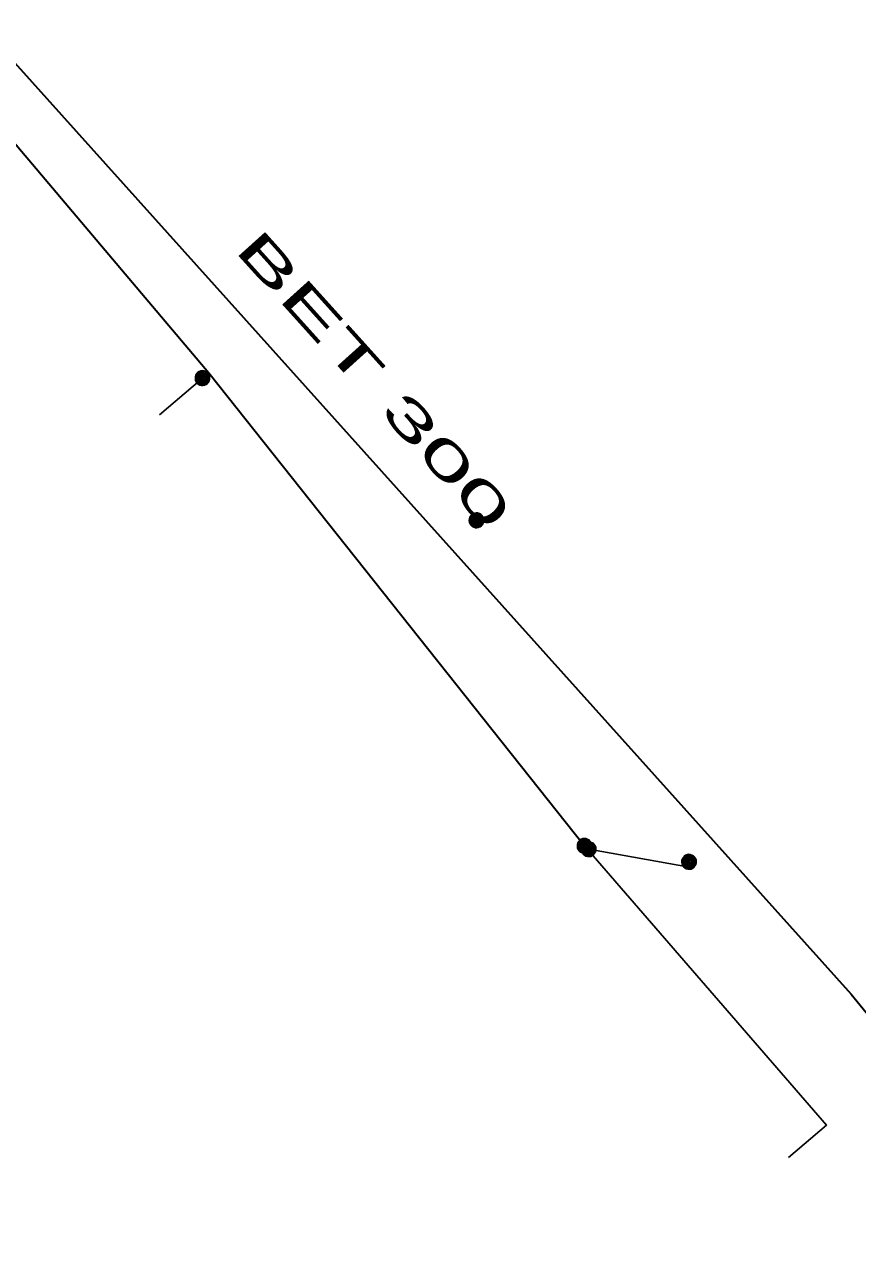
# Model space of a CAD drawing. Extents: x -873619 to -867639, y -1015082 to -1012326.
# Drawn here: x -867922.2 to -867896.54, y -1012817 to -1012778.98 of the extents above; entities that cross this region are included whole.
import ezdxf

# ---------------------------------------------------------------- set-up
doc = ezdxf.new("R2010")
doc.units = 0
doc.header["$LTSCALE"] = 0.44
for name, color, linetype, lineweight in [('1', 7, 'Continuous', 13), ('12', 7, 'Continuous', 13), ('21', 7, 'Continuous', 35), ('25', 7, 'Continuous', 13), ('3', 7, 'Continuous', 25)]:
    doc.layers.add(name, color=color, linetype=linetype, lineweight=lineweight)

msp = doc.modelspace()

# ---------------------------------------------------------------- linework, layer by layer
at = {"layer": '1', "lineweight": 35}
msp.add_lwpolyline([(-867974.611, -1012725.697), (-867974.301, -1012725.775), (-867973.868, -1012725.89), (-867972.988, -1012726.12), (-867972.44, -1012726.34), (-867942.73, -1012759.87), (-867932.66, -1012771.332), (-867928.969, -1012774.977), (-867916.529, -1012789.697), (-867904.95, -1012804.27)], dxfattribs=at)
at = {"layer": '12'}
for points in [[(-867916.489, -1012789.86), (-867916.495, -1012789.808), (-867916.512, -1012789.758), (-867916.541, -1012789.714), (-867916.578, -1012789.677), (-867916.623, -1012789.65), (-867916.673, -1012789.633), (-867916.726, -1012789.629), (-867916.777, -1012789.636), (-867916.826, -1012789.655), (-867916.87, -1012789.684), (-867916.906, -1012789.723), (-867916.932, -1012789.768), (-867916.948, -1012789.819), (-867916.951, -1012789.871), (-867916.943, -1012789.923), (-867916.923, -1012789.972), (-867916.892, -1012790.015), (-867916.853, -1012790.049), (-867916.807, -1012790.075), (-867916.755, -1012790.089), (-867916.703, -1012790.091), (-867916.652, -1012790.081), (-867916.603, -1012790.06), (-867916.561, -1012790.029), (-867916.527, -1012789.988), (-867916.503, -1012789.942), (-867916.49, -1012789.891)], [(-867916.519, -1012789.86), (-867916.525, -1012789.811), (-867916.542, -1012789.765), (-867916.57, -1012789.725), (-867916.607, -1012789.693), (-867916.651, -1012789.671), (-867916.699, -1012789.66), (-867916.748, -1012789.66), (-867916.794, -1012789.673), (-867916.838, -1012789.697), (-867916.874, -1012789.73), (-867916.901, -1012789.771), (-867916.917, -1012789.818), (-867916.921, -1012789.867), (-867916.914, -1012789.915), (-867916.895, -1012789.96), (-867916.865, -1012790), (-867916.826, -1012790.031), (-867916.782, -1012790.051), (-867916.735, -1012790.061), (-867916.686, -1012790.059), (-867916.639, -1012790.044), (-867916.596, -1012790.019), (-867916.561, -1012789.985), (-867916.536, -1012789.943), (-867916.522, -1012789.896)], [(-867916.549, -1012789.86), (-867916.554, -1012789.815), (-867916.571, -1012789.773), (-867916.6, -1012789.738), (-867916.636, -1012789.711), (-867916.678, -1012789.694), (-867916.723, -1012789.689), (-867916.767, -1012789.695), (-867916.809, -1012789.714), (-867916.843, -1012789.742), (-867916.87, -1012789.779), (-867916.887, -1012789.821), (-867916.891, -1012789.866), (-867916.884, -1012789.911), (-867916.865, -1012789.952), (-867916.836, -1012789.986), (-867916.799, -1012790.012), (-867916.755, -1012790.028), (-867916.711, -1012790.031), (-867916.666, -1012790.023), (-867916.625, -1012790.003), (-867916.592, -1012789.974), (-867916.566, -1012789.936), (-867916.552, -1012789.893)], [(-867916.579, -1012789.86), (-867916.583, -1012789.819), (-867916.602, -1012789.782), (-867916.629, -1012789.751), (-867916.664, -1012789.73), (-867916.704, -1012789.719), (-867916.745, -1012789.721), (-867916.784, -1012789.734), (-867916.818, -1012789.758), (-867916.843, -1012789.79), (-867916.858, -1012789.828), (-867916.86, -1012789.869), (-867916.853, -1012789.909), (-867916.833, -1012789.945), (-867916.804, -1012789.974), (-867916.767, -1012789.993), (-867916.727, -1012790.001), (-867916.686, -1012789.997), (-867916.647, -1012789.982), (-867916.615, -1012789.956), (-867916.593, -1012789.922), (-867916.58, -1012789.883)], [(-867916.608, -1012789.86), (-867916.614, -1012789.824), (-867916.632, -1012789.792), (-867916.657, -1012789.767), (-867916.691, -1012789.752), (-867916.728, -1012789.749), (-867916.762, -1012789.757), (-867916.794, -1012789.777), (-867916.816, -1012789.805), (-867916.83, -1012789.839), (-867916.83, -1012789.876), (-867916.819, -1012789.911), (-867916.798, -1012789.94), (-867916.767, -1012789.961), (-867916.733, -1012789.971), (-867916.696, -1012789.969), (-867916.662, -1012789.955), (-867916.635, -1012789.932), (-867916.615, -1012789.9), (-867916.608, -1012789.865)], [(-867916.639, -1012789.86), (-867916.644, -1012789.829), (-867916.661, -1012789.803), (-867916.686, -1012789.786), (-867916.717, -1012789.779), (-867916.748, -1012789.783), (-867916.775, -1012789.8), (-867916.793, -1012789.824), (-867916.801, -1012789.855), (-867916.797, -1012789.885), (-867916.782, -1012789.913), (-867916.757, -1012789.932), (-867916.728, -1012789.941), (-867916.696, -1012789.938), (-867916.669, -1012789.924), (-867916.649, -1012789.9), (-867916.639, -1012789.871)], [(-867916.669, -1012789.86), (-867916.674, -1012789.836), (-867916.691, -1012789.818), (-867916.713, -1012789.809), (-867916.738, -1012789.812), (-867916.759, -1012789.826), (-867916.77, -1012789.848), (-867916.77, -1012789.873), (-867916.757, -1012789.894), (-867916.738, -1012789.908), (-867916.713, -1012789.911), (-867916.69, -1012789.902), (-867916.674, -1012789.884)], [(-867916.699, -1012789.86), (-867916.704, -1012789.845), (-867916.718, -1012789.839), (-867916.733, -1012789.843), (-867916.74, -1012789.857), (-867916.737, -1012789.872), (-867916.723, -1012789.881), (-867916.708, -1012789.878), (-867916.699, -1012789.866)], [(-867904.718, -1012804.27), (-867904.725, -1012804.218), (-867904.742, -1012804.168), (-867904.771, -1012804.124), (-867904.808, -1012804.087), (-867904.853, -1012804.06), (-867904.902, -1012804.043), (-867904.956, -1012804.039), (-867905.007, -1012804.046), (-867905.056, -1012804.065), (-867905.1, -1012804.094), (-867905.136, -1012804.133), (-867905.162, -1012804.178), (-867905.178, -1012804.229), (-867905.181, -1012804.281), (-867905.173, -1012804.333), (-867905.152, -1012804.382), (-867905.122, -1012804.425), (-867905.083, -1012804.459), (-867905.037, -1012804.485), (-867904.985, -1012804.499), (-867904.933, -1012804.501), (-867904.882, -1012804.491), (-867904.833, -1012804.47), (-867904.791, -1012804.439), (-867904.757, -1012804.398), (-867904.733, -1012804.352), (-867904.72, -1012804.301)], [(-867904.749, -1012804.27), (-867904.755, -1012804.221), (-867904.772, -1012804.175), (-867904.799, -1012804.135), (-867904.837, -1012804.103), (-867904.88, -1012804.081), (-867904.929, -1012804.07), (-867904.978, -1012804.07), (-867905.024, -1012804.083), (-867905.068, -1012804.107), (-867905.103, -1012804.14), (-867905.13, -1012804.181), (-867905.147, -1012804.228), (-867905.151, -1012804.277), (-867905.144, -1012804.325), (-867905.125, -1012804.37), (-867905.095, -1012804.41), (-867905.056, -1012804.441), (-867905.012, -1012804.461), (-867904.965, -1012804.471), (-867904.916, -1012804.469), (-867904.869, -1012804.454), (-867904.826, -1012804.429), (-867904.791, -1012804.395), (-867904.766, -1012804.353), (-867904.752, -1012804.306)], [(-867904.779, -1012804.27), (-867904.784, -1012804.225), (-867904.801, -1012804.183), (-867904.83, -1012804.148), (-867904.865, -1012804.121), (-867904.907, -1012804.104), (-867904.953, -1012804.099), (-867904.997, -1012804.105), (-867905.039, -1012804.124), (-867905.073, -1012804.152), (-867905.1, -1012804.189), (-867905.117, -1012804.231), (-867905.12, -1012804.276), (-867905.114, -1012804.321), (-867905.095, -1012804.362), (-867905.066, -1012804.396), (-867905.029, -1012804.422), (-867904.985, -1012804.438), (-867904.941, -1012804.441), (-867904.896, -1012804.433), (-867904.855, -1012804.413), (-867904.821, -1012804.384), (-867904.796, -1012804.346), (-867904.782, -1012804.303)], [(-867904.809, -1012804.27), (-867904.813, -1012804.229), (-867904.831, -1012804.192), (-867904.858, -1012804.161), (-867904.894, -1012804.14), (-867904.934, -1012804.129), (-867904.975, -1012804.131), (-867905.014, -1012804.144), (-867905.048, -1012804.168), (-867905.073, -1012804.2), (-867905.088, -1012804.238), (-867905.09, -1012804.279), (-867905.083, -1012804.319), (-867905.063, -1012804.355), (-867905.034, -1012804.384), (-867904.997, -1012804.403), (-867904.956, -1012804.411), (-867904.916, -1012804.407), (-867904.877, -1012804.392), (-867904.845, -1012804.366), (-867904.823, -1012804.332), (-867904.809, -1012804.293)], [(-867904.838, -1012804.27), (-867904.843, -1012804.234), (-867904.862, -1012804.202), (-867904.887, -1012804.177), (-867904.921, -1012804.162), (-867904.958, -1012804.159), (-867904.992, -1012804.167), (-867905.024, -1012804.187), (-867905.046, -1012804.215), (-867905.059, -1012804.249), (-867905.059, -1012804.286), (-867905.049, -1012804.321), (-867905.027, -1012804.35), (-867904.997, -1012804.371), (-867904.963, -1012804.381), (-867904.926, -1012804.379), (-867904.892, -1012804.365), (-867904.865, -1012804.342), (-867904.845, -1012804.31), (-867904.838, -1012804.275)], [(-867904.588, -1012804.37), (-867904.595, -1012804.318), (-867904.612, -1012804.268), (-867904.641, -1012804.224), (-867904.678, -1012804.187), (-867904.723, -1012804.16), (-867904.772, -1012804.143), (-867904.826, -1012804.139), (-867904.877, -1012804.146), (-867904.926, -1012804.165), (-867904.97, -1012804.194), (-867905.005, -1012804.233), (-867905.032, -1012804.278), (-867905.048, -1012804.329), (-867905.051, -1012804.381), (-867905.043, -1012804.433), (-867905.022, -1012804.482), (-867904.992, -1012804.525), (-867904.953, -1012804.559), (-867904.907, -1012804.585), (-867904.855, -1012804.599), (-867904.803, -1012804.601), (-867904.752, -1012804.591), (-867904.703, -1012804.57), (-867904.661, -1012804.539), (-867904.627, -1012804.498), (-867904.603, -1012804.452), (-867904.59, -1012804.401)], [(-867904.869, -1012804.27), (-867904.874, -1012804.239), (-867904.891, -1012804.213), (-867904.916, -1012804.196), (-867904.946, -1012804.189), (-867904.978, -1012804.193), (-867905.005, -1012804.21), (-867905.022, -1012804.234), (-867905.031, -1012804.265), (-867905.027, -1012804.295), (-867905.012, -1012804.323), (-867904.987, -1012804.342), (-867904.958, -1012804.351), (-867904.926, -1012804.348), (-867904.899, -1012804.334), (-867904.879, -1012804.31), (-867904.869, -1012804.281)], [(-867904.619, -1012804.37), (-867904.625, -1012804.321), (-867904.642, -1012804.275), (-867904.669, -1012804.235), (-867904.706, -1012804.203), (-867904.75, -1012804.181), (-867904.799, -1012804.17), (-867904.848, -1012804.17), (-867904.894, -1012804.183), (-867904.938, -1012804.207), (-867904.973, -1012804.24), (-867905, -1012804.281), (-867905.017, -1012804.328), (-867905.021, -1012804.377), (-867905.014, -1012804.425), (-867904.995, -1012804.47), (-867904.965, -1012804.51), (-867904.926, -1012804.541), (-867904.882, -1012804.561), (-867904.835, -1012804.571), (-867904.786, -1012804.569), (-867904.739, -1012804.554), (-867904.696, -1012804.529), (-867904.661, -1012804.495), (-867904.636, -1012804.453), (-867904.622, -1012804.406)], [(-867904.899, -1012804.27), (-867904.904, -1012804.246), (-867904.921, -1012804.228), (-867904.943, -1012804.219), (-867904.968, -1012804.222), (-867904.989, -1012804.236), (-867905, -1012804.258), (-867905, -1012804.283), (-867904.987, -1012804.304), (-867904.968, -1012804.318), (-867904.943, -1012804.321), (-867904.919, -1012804.312), (-867904.904, -1012804.294)], [(-867904.649, -1012804.37), (-867904.654, -1012804.325), (-867904.671, -1012804.283), (-867904.7, -1012804.248), (-867904.735, -1012804.221), (-867904.777, -1012804.204), (-867904.823, -1012804.199), (-867904.867, -1012804.205), (-867904.909, -1012804.224), (-867904.943, -1012804.252), (-867904.97, -1012804.289), (-867904.987, -1012804.331), (-867904.99, -1012804.376), (-867904.983, -1012804.421), (-867904.965, -1012804.462), (-867904.936, -1012804.496), (-867904.899, -1012804.522), (-867904.855, -1012804.538), (-867904.811, -1012804.541), (-867904.766, -1012804.533), (-867904.725, -1012804.513), (-867904.691, -1012804.484), (-867904.666, -1012804.446), (-867904.652, -1012804.403)], [(-867904.929, -1012804.27), (-867904.934, -1012804.255), (-867904.948, -1012804.249), (-867904.963, -1012804.253), (-867904.97, -1012804.267), (-867904.967, -1012804.282), (-867904.953, -1012804.291), (-867904.938, -1012804.288), (-867904.929, -1012804.276)], [(-867904.679, -1012804.37), (-867904.683, -1012804.329), (-867904.701, -1012804.292), (-867904.728, -1012804.261), (-867904.764, -1012804.24), (-867904.804, -1012804.229), (-867904.845, -1012804.231), (-867904.884, -1012804.244), (-867904.918, -1012804.268), (-867904.943, -1012804.3), (-867904.958, -1012804.338), (-867904.96, -1012804.379), (-867904.953, -1012804.419), (-867904.933, -1012804.455), (-867904.904, -1012804.484), (-867904.867, -1012804.503), (-867904.826, -1012804.511), (-867904.786, -1012804.507), (-867904.747, -1012804.492), (-867904.715, -1012804.466), (-867904.693, -1012804.432), (-867904.679, -1012804.393)], [(-867904.708, -1012804.37), (-867904.713, -1012804.334), (-867904.732, -1012804.302), (-867904.757, -1012804.277), (-867904.791, -1012804.262), (-867904.828, -1012804.259), (-867904.862, -1012804.267), (-867904.894, -1012804.287), (-867904.916, -1012804.315), (-867904.929, -1012804.349), (-867904.929, -1012804.386), (-867904.919, -1012804.421), (-867904.897, -1012804.45), (-867904.867, -1012804.471), (-867904.833, -1012804.481), (-867904.796, -1012804.479), (-867904.762, -1012804.465), (-867904.735, -1012804.442), (-867904.715, -1012804.41), (-867904.708, -1012804.375)], [(-867904.739, -1012804.37), (-867904.744, -1012804.339), (-867904.761, -1012804.313), (-867904.786, -1012804.296), (-867904.816, -1012804.289), (-867904.848, -1012804.293), (-867904.875, -1012804.31), (-867904.892, -1012804.334), (-867904.901, -1012804.365), (-867904.897, -1012804.395), (-867904.882, -1012804.423), (-867904.857, -1012804.442), (-867904.828, -1012804.451), (-867904.796, -1012804.448), (-867904.769, -1012804.434), (-867904.749, -1012804.41), (-867904.739, -1012804.381)], [(-867904.769, -1012804.37), (-867904.774, -1012804.346), (-867904.791, -1012804.328), (-867904.813, -1012804.319), (-867904.838, -1012804.322), (-867904.858, -1012804.336), (-867904.87, -1012804.358), (-867904.87, -1012804.383), (-867904.857, -1012804.404), (-867904.838, -1012804.418), (-867904.813, -1012804.421), (-867904.789, -1012804.412), (-867904.774, -1012804.394)], [(-867904.799, -1012804.37), (-867904.804, -1012804.355), (-867904.818, -1012804.349), (-867904.833, -1012804.353), (-867904.84, -1012804.367), (-867904.837, -1012804.382), (-867904.823, -1012804.391), (-867904.808, -1012804.388), (-867904.799, -1012804.376)]]:
    msp.add_lwpolyline(points, close=True, dxfattribs=at)
at = {"layer": '21'}
msp.add_lwpolyline([(-867931.383, -1012770.263), (-867896.732, -1012808.835), (-867867.37, -1012844.68)], dxfattribs=at)
at = {"layer": '25'}
for points in [[(-867908.049, -1012794.24), (-867908.055, -1012794.188), (-867908.072, -1012794.138), (-867908.101, -1012794.094), (-867908.138, -1012794.057), (-867908.183, -1012794.03), (-867908.233, -1012794.013), (-867908.286, -1012794.009), (-867908.338, -1012794.016), (-867908.387, -1012794.035), (-867908.43, -1012794.064), (-867908.466, -1012794.103), (-867908.492, -1012794.148), (-867908.508, -1012794.199), (-867908.511, -1012794.251), (-867908.503, -1012794.303), (-867908.483, -1012794.352), (-867908.452, -1012794.395), (-867908.413, -1012794.429), (-867908.367, -1012794.455), (-867908.316, -1012794.469), (-867908.263, -1012794.471), (-867908.212, -1012794.461), (-867908.164, -1012794.44), (-867908.121, -1012794.409), (-867908.087, -1012794.368), (-867908.063, -1012794.322), (-867908.051, -1012794.271)], [(-867908.079, -1012794.24), (-867908.085, -1012794.191), (-867908.102, -1012794.145), (-867908.13, -1012794.105), (-867908.167, -1012794.073), (-867908.211, -1012794.051), (-867908.259, -1012794.04), (-867908.308, -1012794.04), (-867908.355, -1012794.053), (-867908.398, -1012794.077), (-867908.434, -1012794.11), (-867908.461, -1012794.151), (-867908.477, -1012794.198), (-867908.481, -1012794.247), (-867908.474, -1012794.295), (-867908.455, -1012794.34), (-867908.425, -1012794.38), (-867908.387, -1012794.411), (-867908.343, -1012794.431), (-867908.295, -1012794.441), (-867908.246, -1012794.439), (-867908.199, -1012794.424), (-867908.156, -1012794.399), (-867908.122, -1012794.365), (-867908.096, -1012794.323), (-867908.082, -1012794.276)], [(-867908.109, -1012794.24), (-867908.115, -1012794.195), (-867908.132, -1012794.153), (-867908.16, -1012794.118), (-867908.196, -1012794.091), (-867908.238, -1012794.074), (-867908.283, -1012794.069), (-867908.328, -1012794.075), (-867908.369, -1012794.094), (-867908.404, -1012794.122), (-867908.431, -1012794.159), (-867908.447, -1012794.201), (-867908.451, -1012794.246), (-867908.444, -1012794.291), (-867908.425, -1012794.332), (-867908.396, -1012794.366), (-867908.359, -1012794.392), (-867908.316, -1012794.408), (-867908.271, -1012794.411), (-867908.226, -1012794.403), (-867908.186, -1012794.383), (-867908.152, -1012794.354), (-867908.126, -1012794.316), (-867908.112, -1012794.273)], [(-867908.139, -1012794.24), (-867908.144, -1012794.199), (-867908.162, -1012794.162), (-867908.189, -1012794.131), (-867908.224, -1012794.11), (-867908.264, -1012794.099), (-867908.305, -1012794.101), (-867908.344, -1012794.114), (-867908.378, -1012794.138), (-867908.403, -1012794.17), (-867908.418, -1012794.208), (-867908.421, -1012794.249), (-867908.413, -1012794.289), (-867908.393, -1012794.325), (-867908.364, -1012794.354), (-867908.327, -1012794.373), (-867908.287, -1012794.381), (-867908.246, -1012794.377), (-867908.208, -1012794.362), (-867908.176, -1012794.336), (-867908.153, -1012794.302), (-867908.14, -1012794.263)], [(-867908.169, -1012794.24), (-867908.174, -1012794.204), (-867908.192, -1012794.172), (-867908.218, -1012794.147), (-867908.252, -1012794.132), (-867908.288, -1012794.129), (-867908.323, -1012794.137), (-867908.354, -1012794.157), (-867908.377, -1012794.185), (-867908.39, -1012794.219), (-867908.39, -1012794.256), (-867908.379, -1012794.291), (-867908.358, -1012794.32), (-867908.328, -1012794.341), (-867908.293, -1012794.351), (-867908.256, -1012794.349), (-867908.222, -1012794.335), (-867908.195, -1012794.312), (-867908.176, -1012794.28), (-867908.169, -1012794.245)], [(-867908.199, -1012794.24), (-867908.204, -1012794.209), (-867908.221, -1012794.183), (-867908.247, -1012794.166), (-867908.277, -1012794.159), (-867908.308, -1012794.163), (-867908.335, -1012794.18), (-867908.353, -1012794.204), (-867908.361, -1012794.235), (-867908.357, -1012794.265), (-867908.342, -1012794.293), (-867908.318, -1012794.312), (-867908.288, -1012794.321), (-867908.257, -1012794.318), (-867908.229, -1012794.304), (-867908.209, -1012794.28), (-867908.199, -1012794.251)], [(-867908.229, -1012794.24), (-867908.234, -1012794.216), (-867908.251, -1012794.198), (-867908.274, -1012794.189), (-867908.298, -1012794.192), (-867908.319, -1012794.206), (-867908.33, -1012794.228), (-867908.33, -1012794.253), (-867908.318, -1012794.274), (-867908.298, -1012794.288), (-867908.273, -1012794.291), (-867908.25, -1012794.282), (-867908.234, -1012794.264)], [(-867908.259, -1012794.24), (-867908.264, -1012794.225), (-867908.279, -1012794.219), (-867908.294, -1012794.223), (-867908.301, -1012794.237), (-867908.297, -1012794.252), (-867908.284, -1012794.261), (-867908.269, -1012794.258), (-867908.259, -1012794.246)], [(-867901.498, -1012804.76), (-867901.504, -1012804.708), (-867901.521, -1012804.658), (-867901.55, -1012804.614), (-867901.587, -1012804.577), (-867901.632, -1012804.55), (-867901.682, -1012804.533), (-867901.735, -1012804.529), (-867901.787, -1012804.536), (-867901.836, -1012804.555), (-867901.879, -1012804.584), (-867901.915, -1012804.623), (-867901.941, -1012804.668), (-867901.957, -1012804.719), (-867901.96, -1012804.771), (-867901.952, -1012804.823), (-867901.932, -1012804.872), (-867901.901, -1012804.915), (-867901.862, -1012804.949), (-867901.816, -1012804.975), (-867901.765, -1012804.989), (-867901.712, -1012804.991), (-867901.661, -1012804.981), (-867901.613, -1012804.96), (-867901.57, -1012804.929), (-867901.536, -1012804.888), (-867901.512, -1012804.842), (-867901.5, -1012804.791)], [(-867901.528, -1012804.76), (-867901.534, -1012804.711), (-867901.551, -1012804.665), (-867901.579, -1012804.625), (-867901.616, -1012804.593), (-867901.66, -1012804.571), (-867901.708, -1012804.56), (-867901.757, -1012804.56), (-867901.804, -1012804.573), (-867901.847, -1012804.597), (-867901.883, -1012804.63), (-867901.91, -1012804.671), (-867901.926, -1012804.718), (-867901.93, -1012804.767), (-867901.923, -1012804.815), (-867901.904, -1012804.86), (-867901.874, -1012804.9), (-867901.836, -1012804.931), (-867901.792, -1012804.951), (-867901.744, -1012804.961), (-867901.695, -1012804.959), (-867901.648, -1012804.944), (-867901.605, -1012804.919), (-867901.571, -1012804.885), (-867901.545, -1012804.843), (-867901.531, -1012804.796)], [(-867901.558, -1012804.76), (-867901.564, -1012804.715), (-867901.581, -1012804.673), (-867901.609, -1012804.638), (-867901.645, -1012804.611), (-867901.687, -1012804.594), (-867901.732, -1012804.589), (-867901.777, -1012804.595), (-867901.818, -1012804.614), (-867901.853, -1012804.642), (-867901.88, -1012804.679), (-867901.896, -1012804.721), (-867901.9, -1012804.766), (-867901.893, -1012804.811), (-867901.874, -1012804.852), (-867901.845, -1012804.886), (-867901.808, -1012804.912), (-867901.765, -1012804.928), (-867901.72, -1012804.931), (-867901.675, -1012804.923), (-867901.635, -1012804.903), (-867901.601, -1012804.874), (-867901.575, -1012804.836), (-867901.561, -1012804.793)], [(-867901.588, -1012804.76), (-867901.593, -1012804.719), (-867901.611, -1012804.682), (-867901.638, -1012804.651), (-867901.673, -1012804.63), (-867901.713, -1012804.619), (-867901.754, -1012804.621), (-867901.793, -1012804.634), (-867901.827, -1012804.658), (-867901.852, -1012804.69), (-867901.867, -1012804.728), (-867901.87, -1012804.769), (-867901.862, -1012804.809), (-867901.842, -1012804.845), (-867901.813, -1012804.874), (-867901.776, -1012804.893), (-867901.736, -1012804.901), (-867901.695, -1012804.897), (-867901.657, -1012804.882), (-867901.625, -1012804.856), (-867901.602, -1012804.822), (-867901.589, -1012804.783)], [(-867901.618, -1012804.76), (-867901.623, -1012804.724), (-867901.641, -1012804.692), (-867901.667, -1012804.667), (-867901.701, -1012804.652), (-867901.737, -1012804.649), (-867901.772, -1012804.657), (-867901.803, -1012804.677), (-867901.826, -1012804.705), (-867901.839, -1012804.739), (-867901.839, -1012804.776), (-867901.828, -1012804.811), (-867901.807, -1012804.84), (-867901.777, -1012804.861), (-867901.742, -1012804.871), (-867901.705, -1012804.869), (-867901.671, -1012804.855), (-867901.644, -1012804.832), (-867901.625, -1012804.8), (-867901.618, -1012804.765)], [(-867901.648, -1012804.76), (-867901.653, -1012804.729), (-867901.67, -1012804.703), (-867901.696, -1012804.686), (-867901.726, -1012804.679), (-867901.757, -1012804.683), (-867901.784, -1012804.7), (-867901.802, -1012804.724), (-867901.81, -1012804.755), (-867901.806, -1012804.785), (-867901.791, -1012804.813), (-867901.767, -1012804.832), (-867901.737, -1012804.841), (-867901.706, -1012804.838), (-867901.678, -1012804.824), (-867901.658, -1012804.8), (-867901.648, -1012804.771)], [(-867901.678, -1012804.76), (-867901.683, -1012804.736), (-867901.7, -1012804.718), (-867901.723, -1012804.709), (-867901.747, -1012804.712), (-867901.768, -1012804.726), (-867901.779, -1012804.748), (-867901.779, -1012804.773), (-867901.767, -1012804.794), (-867901.747, -1012804.808), (-867901.722, -1012804.811), (-867901.699, -1012804.802), (-867901.683, -1012804.784)], [(-867901.708, -1012804.76), (-867901.713, -1012804.745), (-867901.728, -1012804.739), (-867901.743, -1012804.743), (-867901.75, -1012804.757), (-867901.746, -1012804.772), (-867901.733, -1012804.781), (-867901.718, -1012804.778), (-867901.708, -1012804.766)]]:
    msp.add_lwpolyline(points, close=True, dxfattribs=at)
at = {"layer": '3'}
msp.add_line((-867916.529, -1012789.697), (-867918.043, -1012790.99), dxfattribs=at)
for points in [[(-867904.95, -1012804.27), (-867897.49, -1012812.87), (-867898.67, -1012813.869)], [(-867904.95, -1012804.27), (-867904.82, -1012804.37), (-867901.66, -1012804.93)]]:
    msp.add_lwpolyline(points, dxfattribs=at)

# ---------------------------------------------------------------- texts
at = {"layer": '1', "width": 2.05}
msp.add_text('BET 300 ', height=1.1, rotation=312, dxfattribs=at).set_placement((-867915.775, -1012785.916))

doc.saveas('drawing.dxf')
